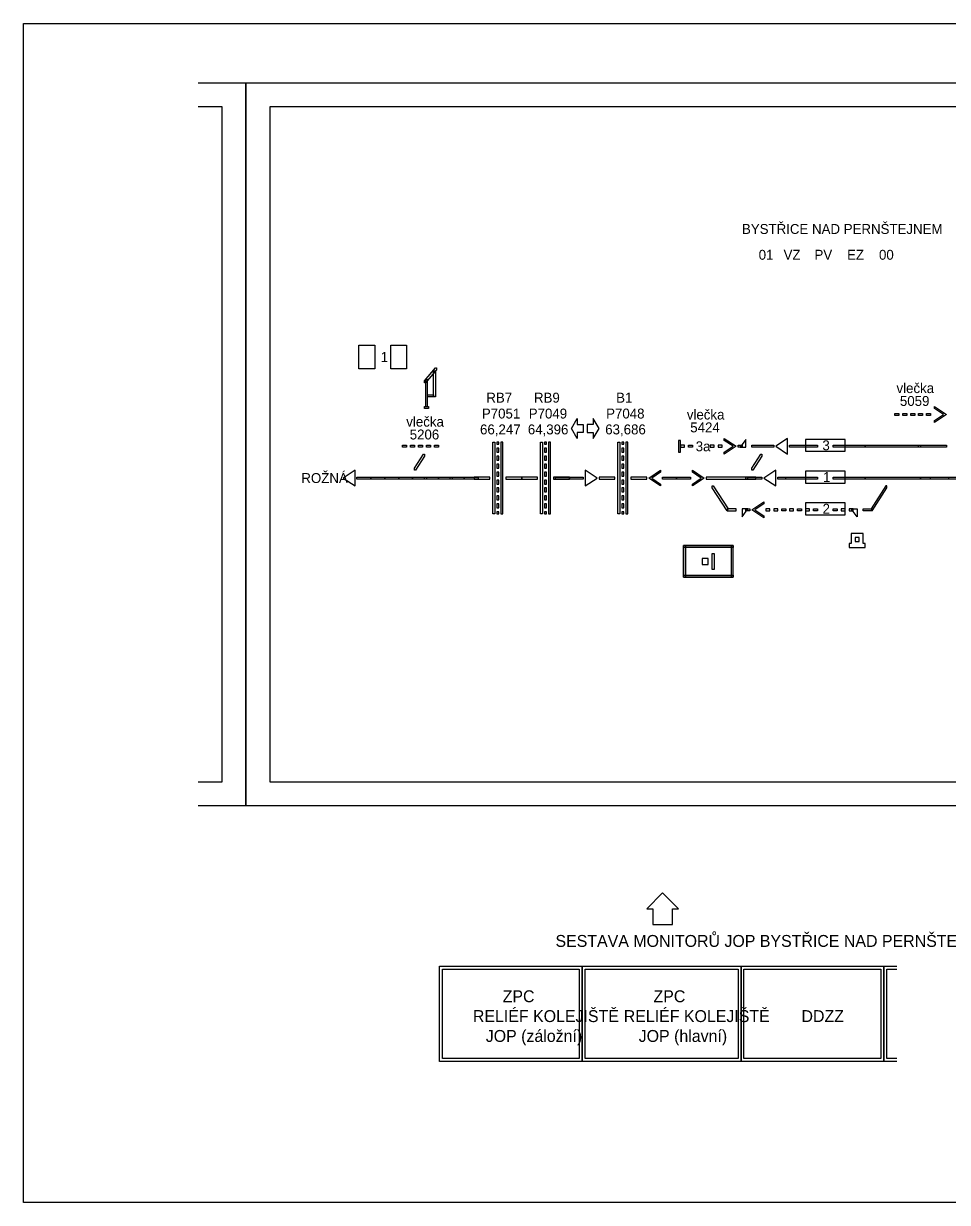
# Model space of a CAD drawing. Extents: x -1424 to 5155, y -2900 to 2050.
# Drawn here: x 2740 to 2972.8, y -2350 to -2053 of the extents above; entities that cross this region are included whole.
import ezdxf

# ---------------------------------------------------------------- set-up
doc = ezdxf.new("R2010")
doc.units = 0
doc.layers.add('Vrstva 1', color=7, linetype='Continuous')
doc.layers.add('Vrstva 2', color=7, linetype='Continuous')

msp = doc.modelspace()

# ---------------------------------------------------------------- linework, layer by layer
for points in [[(2784, -2250), (2796, -2250), (2796, -2068), (2784, -2068)], [(2784, -2244), (2790, -2244), (2790, -2074), (2784, -2074)], [(2960, -2314.5), (2956.75, -2314.5), (2956.75, -2290.5), (2960, -2290.5)], [(2960, -2313.75), (2957.5, -2313.75), (2957.5, -2291.25), (2960, -2291.25)]]:
    msp.add_lwpolyline(points)
for points in [[(2796, -2250), (3108, -2250), (3108, -2068), (2796, -2068)], [(2802, -2244), (3102, -2244), (3102, -2074), (2802, -2074)], [(2901, -2272), (2897, -2276), (2898.5, -2276), (2898.5, -2280), (2903.5, -2280), (2903.5, -2276), (2905, -2276)], [(2844.75, -2290.5), (2880.75, -2290.5), (2880.75, -2314.5), (2844.75, -2314.5)], [(2845.5, -2291.25), (2880, -2291.25), (2880, -2313.75), (2845.5, -2313.75)], [(2880.75, -2290.5), (2920.75, -2290.5), (2920.75, -2314.5), (2880.75, -2314.5)], [(2881.5, -2291.25), (2920, -2291.25), (2920, -2313.75), (2881.5, -2313.75)], [(2920.75, -2290.5), (2956.75, -2290.5), (2956.75, -2314.5), (2920.75, -2314.5)], [(2921.5, -2291.25), (2956, -2291.25), (2956, -2313.75), (2921.5, -2313.75)]]:
    msp.add_lwpolyline(points, close=True)
at = {"layer": 'Vrstva 1'}
for points in [[(3160, -2350), (2740, -2350), (2740, -2053), (3160, -2053)], [(2841.25, -2143.5), (2841, -2143.5), (2841, -2143), (2843.75, -2139.75), (2844, -2139.75), (2844, -2140.25)], [(2843.25, -2140.5), (2843.75, -2140.5), (2843.75, -2147), (2843.25, -2147)], [(2841, -2143.5), (2841.25, -2143.25), (2841.25, -2143.25), (2841.25, -2143.25)], [(2841.75, -2142.75), (2841.25, -2142.75), (2841.25, -2149.5), (2841.75, -2149.5)], [(2841.75, -2146.5), (2843.25, -2146.5), (2843.25, -2147), (2841.75, -2147)], [(2841, -2149.5), (2842, -2149.5), (2842, -2150), (2841, -2150)], [(2969.5, -2149.5), (2972.5, -2151.5), (2969.5, -2153.5), (2969.5, -2153), (2971.75, -2151.5), (2969.5, -2150)], [(2881, -2154), (2881, -2156), (2879.5, -2156), (2879.5, -2157.5), (2878, -2155), (2879.5, -2152.5), (2879.5, -2154)], [(2882, -2154), (2882, -2156), (2883.5, -2156), (2883.5, -2157.5), (2885, -2155), (2883.5, -2152.5), (2883.5, -2154)], [(2960.5, -2151.75), (2959.5, -2151.75), (2959.5, -2151.25), (2960.5, -2151.25)], [(2962.5, -2151.75), (2961.5, -2151.75), (2961.5, -2151.25), (2962.5, -2151.25)], [(2964.5, -2151.75), (2963.5, -2151.75), (2963.5, -2151.25), (2964.5, -2151.25)], [(2966.5, -2151.75), (2965.5, -2151.75), (2965.5, -2151.25), (2966.5, -2151.25)], [(2968.5, -2151.75), (2967.5, -2151.75), (2967.5, -2151.25), (2968.5, -2151.25)], [(2858.75, -2176.5), (2858.25, -2176.5), (2858.25, -2158.5), (2858.75, -2158.5)], [(2859.75, -2158.5), (2859.25, -2158.5), (2859.25, -2159), (2859.75, -2159)], [(2860.75, -2158.5), (2860.25, -2158.5), (2860.25, -2176.5), (2860.75, -2176.5)], [(2870.75, -2176.5), (2870.25, -2176.5), (2870.25, -2158.5), (2870.75, -2158.5)], [(2871.75, -2158.5), (2871.25, -2158.5), (2871.25, -2159), (2871.75, -2159)], [(2872.75, -2158.5), (2872.25, -2158.5), (2872.25, -2176.5), (2872.75, -2176.5)], [(2890.25, -2176.5), (2889.75, -2176.5), (2889.75, -2158.5), (2890.25, -2158.5)], [(2891.25, -2158.5), (2890.75, -2158.5), (2890.75, -2159), (2891.25, -2159)], [(2892.25, -2158.5), (2891.75, -2158.5), (2891.75, -2176.5), (2892.25, -2176.5)], [(2905, -2161), (2905.5, -2161), (2905.5, -2158), (2905, -2158)], [(2916.5, -2157.5), (2919.5, -2159.5), (2916.5, -2161.5), (2916.5, -2161), (2918.75, -2159.5), (2916.5, -2158)], [(2922, -2159.75), (2922, -2157.75), (2920.5, -2159.75)], [(2922, -2159.75), (2922, -2157.75), (2920.5, -2159.75)], [(2932.5, -2161.5), (2932.5, -2157.5), (2929.5, -2159.5)], [(2937, -2160.75), (2947, -2160.75), (2947, -2157.75), (2937, -2157.75)], [(2937, -2160.75), (2947, -2160.75), (2947, -2157.75), (2937, -2157.75)], [(2836.5, -2159.75), (2835.5, -2159.75), (2835.5, -2159.25), (2836.5, -2159.25)], [(2838.5, -2159.75), (2837.5, -2159.75), (2837.5, -2159.25), (2838.5, -2159.25)], [(2838.5, -2165.5), (2838.5, -2165), (2840.75, -2161.5), (2841, -2161.5), (2841, -2162), (2838.75, -2165.5)], [(2840.5, -2159.75), (2839.5, -2159.75), (2839.5, -2159.25), (2840.5, -2159.25)], [(2842.5, -2159.75), (2841.5, -2159.75), (2841.5, -2159.25), (2842.5, -2159.25)], [(2844.5, -2159.75), (2843.5, -2159.75), (2843.5, -2159.25), (2844.5, -2159.25)], [(2859.75, -2160), (2859.25, -2160), (2859.25, -2161), (2859.75, -2161)], [(2859.75, -2162), (2859.25, -2162), (2859.25, -2163), (2859.75, -2163)], [(2871.75, -2160), (2871.25, -2160), (2871.25, -2161), (2871.75, -2161)], [(2871.75, -2162), (2871.25, -2162), (2871.25, -2163), (2871.75, -2163)], [(2891.25, -2160), (2890.75, -2160), (2890.75, -2161), (2891.25, -2161)], [(2891.25, -2162), (2890.75, -2162), (2890.75, -2163), (2891.25, -2163)], [(2905.49, -2159.75), (2906.49, -2159.75), (2906.49, -2159.25), (2905.49, -2159.25)], [(2905.49, -2159.75), (2906.49, -2159.75), (2906.49, -2159.25), (2905.49, -2159.25)], [(2907.5, -2159.25), (2908.5, -2159.25), (2908.5, -2159.75), (2907.5, -2159.75)], [(2907.5, -2159.25), (2908.5, -2159.25), (2908.5, -2159.75), (2907.5, -2159.75)], [(2907.5, -2159.25), (2908.5, -2159.25), (2908.5, -2159.75), (2907.5, -2159.75)], [(2912.99, -2159.75), (2913.99, -2159.75), (2913.99, -2159.25), (2912.99, -2159.25)], [(2914.99, -2159.75), (2915.99, -2159.75), (2915.99, -2159.25), (2914.99, -2159.25)], [(2921, -2159.75), (2920, -2159.75), (2920, -2159.25), (2921, -2159.25)], [(2921, -2159.75), (2920, -2159.75), (2920, -2159.25), (2921, -2159.25)], [(2929, -2159.75), (2923.5, -2159.75), (2923.5, -2159.25), (2929, -2159.25)], [(2923.5, -2165.5), (2923.5, -2165), (2925.75, -2161.5), (2926, -2161.5), (2926, -2162), (2923.75, -2165.5)], [(2940, -2159.75), (2933, -2159.75), (2933, -2159.25), (2940, -2159.25)], [(2952, -2159.75), (2944, -2159.75), (2944, -2159.25), (2952, -2159.25)], [(2966, -2159.75), (2952, -2159.75), (2952, -2159.25), (2966, -2159.25)], [(2972.5, -2159.75), (2965.5, -2159.75), (2965.5, -2159.25), (2972.5, -2159.25)], [(2859.75, -2164), (2859.25, -2164), (2859.25, -2165), (2859.75, -2165)], [(2871.75, -2164), (2871.25, -2164), (2871.25, -2165), (2871.75, -2165)], [(2891.25, -2164), (2890.75, -2164), (2890.75, -2165), (2891.25, -2165)], [(2823.5, -2169.5), (2823.5, -2165.5), (2820.5, -2167.5)], [(2827.5, -2167.75), (2824, -2167.75), (2824, -2167.25), (2827.5, -2167.25)], [(2831, -2167.75), (2827.5, -2167.75), (2827.5, -2167.25), (2831, -2167.25)], [(2834.5, -2167.75), (2831, -2167.75), (2831, -2167.25), (2834.5, -2167.25)], [(2838, -2167.75), (2834.5, -2167.75), (2834.5, -2167.25), (2838, -2167.25)], [(2841.5, -2167.75), (2838, -2167.75), (2838, -2167.25), (2841.5, -2167.25)], [(2844.5, -2167.75), (2841, -2167.75), (2841, -2167.25), (2844.5, -2167.25)], [(2848, -2167.75), (2844.5, -2167.75), (2844.5, -2167.25), (2848, -2167.25)], [(2851, -2167.75), (2847.5, -2167.75), (2847.5, -2167.25), (2851, -2167.25)], [(2854.5, -2167.75), (2851, -2167.75), (2851, -2167.25), (2854.5, -2167.25)], [(2857.5, -2167.25), (2853.5, -2167.25), (2853.5, -2167.75), (2857.5, -2167.75)], [(2859.75, -2166), (2859.25, -2166), (2859.25, -2167), (2859.75, -2167)], [(2859.75, -2168), (2859.25, -2168), (2859.25, -2169), (2859.75, -2169)], [(2865.5, -2167.25), (2861.5, -2167.25), (2861.5, -2167.75), (2865.5, -2167.75)], [(2869.5, -2167.25), (2865.5, -2167.25), (2865.5, -2167.75), (2869.5, -2167.75)], [(2871.75, -2166), (2871.25, -2166), (2871.25, -2167), (2871.75, -2167)], [(2871.75, -2168), (2871.25, -2168), (2871.25, -2169), (2871.75, -2169)], [(2877.5, -2167.25), (2873.5, -2167.25), (2873.5, -2167.75), (2877.5, -2167.75)], [(2877.5, -2167.75), (2874, -2167.75), (2874, -2167.25), (2877.5, -2167.25)], [(2881, -2167.75), (2877.5, -2167.75), (2877.5, -2167.25), (2881, -2167.25)], [(2881.5, -2165.5), (2881.5, -2169.5), (2884.5, -2167.5)], [(2881.5, -2165.5), (2881.5, -2169.5), (2884.5, -2167.5)], [(2889, -2167.25), (2885, -2167.25), (2885, -2167.75), (2889, -2167.75)], [(2891.25, -2166), (2890.75, -2166), (2890.75, -2167), (2891.25, -2167)], [(2891.25, -2168), (2890.75, -2168), (2890.75, -2169), (2891.25, -2169)], [(2897, -2167.25), (2893, -2167.25), (2893, -2167.75), (2897, -2167.75)], [(2900.5, -2169.5), (2897.5, -2167.5), (2900.5, -2165.5), (2900.5, -2166), (2898.25, -2167.5), (2900.5, -2169)], [(2904.5, -2167.75), (2901, -2167.75), (2901, -2167.25), (2904.5, -2167.25)], [(2908, -2167.75), (2904.5, -2167.75), (2904.5, -2167.25), (2908, -2167.25)], [(2908, -2167.75), (2904.5, -2167.75), (2904.5, -2167.25), (2908, -2167.25)], [(2908.5, -2165.5), (2911.5, -2167.5), (2908.5, -2169.5), (2908.5, -2169), (2910.75, -2167.5), (2908.5, -2166)], [(2908.5, -2165.5), (2911.5, -2167.5), (2908.5, -2169.5), (2908.5, -2169), (2910.75, -2167.5), (2908.5, -2166)], [(2912, -2167.75), (2922, -2167.75), (2922, -2167.25), (2912, -2167.25)], [(2924.5, -2167.25), (2922, -2167.25), (2922, -2167.75), (2924.5, -2167.75)], [(2926, -2167.75), (2922.5, -2167.75), (2922.5, -2167.25), (2926, -2167.25)], [(2929.5, -2169.5), (2929.5, -2165.5), (2926.5, -2167.5)], [(2940, -2167.75), (2930, -2167.75), (2930, -2167.25), (2940, -2167.25)], [(2940, -2167.75), (2932, -2167.75), (2932, -2167.25), (2940, -2167.25)], [(2937, -2168.75), (2947, -2168.75), (2947, -2165.75), (2937, -2165.75)], [(2937, -2168.75), (2947, -2168.75), (2947, -2165.75), (2937, -2165.75)], [(2952, -2167.75), (2944, -2167.75), (2944, -2167.25), (2952, -2167.25)], [(2966, -2167.75), (2952, -2167.75), (2952, -2167.25), (2966, -2167.25)], [(2973, -2167.75), (2966, -2167.75), (2966, -2167.25), (2973, -2167.25)], [(2975.5, -2167.75), (2968.5, -2167.75), (2968.5, -2167.25), (2975.5, -2167.25)], [(2859.75, -2170), (2859.25, -2170), (2859.25, -2171), (2859.75, -2171)], [(2871.75, -2170), (2871.25, -2170), (2871.25, -2171), (2871.75, -2171)], [(2891.25, -2170), (2890.75, -2170), (2890.75, -2171), (2891.25, -2171)], [(2913.5, -2170), (2913.5, -2169.5), (2913.75, -2169.5), (2917.5, -2175.25), (2917.25, -2175.75)], [(2913.5, -2170), (2913.5, -2169.5), (2913.75, -2169.5), (2917.5, -2175.25), (2917.25, -2175.75)], [(2957.5, -2170), (2957.5, -2169.5), (2957.25, -2169.5), (2953.5, -2175.25), (2953.75, -2175.75)], [(2859.75, -2172), (2859.25, -2172), (2859.25, -2173), (2859.75, -2173)], [(2859.75, -2174), (2859.25, -2174), (2859.25, -2175), (2859.75, -2175)], [(2871.75, -2172), (2871.25, -2172), (2871.25, -2173), (2871.75, -2173)], [(2871.75, -2174), (2871.25, -2174), (2871.25, -2175), (2871.75, -2175)], [(2891.25, -2172), (2890.75, -2172), (2890.75, -2173), (2891.25, -2173)], [(2891.25, -2174), (2890.75, -2174), (2890.75, -2175), (2891.25, -2175)], [(2926.5, -2177.5), (2923.5, -2175.5), (2926.5, -2173.5), (2926.5, -2174), (2924.25, -2175.5), (2926.5, -2177)], [(2937, -2176.75), (2947, -2176.75), (2947, -2173.75), (2937, -2173.75)], [(2937, -2176.75), (2947, -2176.75), (2947, -2173.75), (2937, -2173.75)], [(2859.75, -2176), (2859.25, -2176), (2859.25, -2176.5), (2859.75, -2176.5)], [(2871.75, -2176), (2871.25, -2176), (2871.25, -2176.5), (2871.75, -2176.5)], [(2891.25, -2176), (2890.75, -2176), (2890.75, -2176.5), (2891.25, -2176.5)], [(2919.5, -2175.25), (2917.25, -2175.25), (2917.25, -2175.75), (2919.5, -2175.75)], [(2921, -2175.25), (2921, -2177.25), (2922.5, -2175.25)], [(2921, -2175.25), (2921, -2177.25), (2922.5, -2175.25)], [(2922, -2175.25), (2923, -2175.25), (2923, -2175.75), (2922, -2175.75)], [(2922, -2175.25), (2923, -2175.25), (2923, -2175.75), (2922, -2175.75)], [(2926.99, -2175.75), (2927.99, -2175.75), (2927.99, -2175.25), (2926.99, -2175.25)], [(2926.99, -2175.75), (2927.99, -2175.75), (2927.99, -2175.25), (2926.99, -2175.25)], [(2928.99, -2175.75), (2929.99, -2175.75), (2929.99, -2175.25), (2928.99, -2175.25)], [(2931, -2175.25), (2932, -2175.25), (2932, -2175.75), (2931, -2175.75)], [(2931, -2175.25), (2932, -2175.25), (2932, -2175.75), (2931, -2175.75)], [(2931, -2175.25), (2932, -2175.25), (2932, -2175.75), (2931, -2175.75)], [(2931, -2175.25), (2932, -2175.25), (2932, -2175.75), (2931, -2175.75)], [(2932.99, -2175.75), (2933.99, -2175.75), (2933.99, -2175.25), (2932.99, -2175.25)], [(2932.99, -2175.75), (2933.99, -2175.75), (2933.99, -2175.25), (2932.99, -2175.25)], [(2935, -2175.25), (2936, -2175.25), (2936, -2175.75), (2935, -2175.75)], [(2935, -2175.25), (2936, -2175.25), (2936, -2175.75), (2935, -2175.75)], [(2935, -2175.25), (2936, -2175.25), (2936, -2175.75), (2935, -2175.75)], [(2935, -2175.25), (2936, -2175.25), (2936, -2175.75), (2935, -2175.75)], [(2936.99, -2175.75), (2937.99, -2175.75), (2937.99, -2175.25), (2936.99, -2175.25)], [(2936.99, -2175.75), (2937.99, -2175.75), (2937.99, -2175.25), (2936.99, -2175.25)], [(2939, -2175.25), (2940, -2175.25), (2940, -2175.75), (2939, -2175.75)], [(2939, -2175.25), (2940, -2175.25), (2940, -2175.75), (2939, -2175.75)], [(2939, -2175.25), (2940, -2175.25), (2940, -2175.75), (2939, -2175.75)], [(2939, -2175.25), (2940, -2175.25), (2940, -2175.75), (2939, -2175.75)], [(2944, -2175.25), (2945, -2175.25), (2945, -2175.75), (2944, -2175.75)], [(2944, -2175.25), (2945, -2175.25), (2945, -2175.75), (2944, -2175.75)], [(2947, -2175.25), (2946, -2175.25), (2946, -2175.75), (2947, -2175.75)], [(2947, -2175.25), (2946, -2175.25), (2946, -2175.75), (2947, -2175.75)], [(2949, -2175.25), (2948, -2175.25), (2948, -2175.75), (2949, -2175.75)], [(2949, -2175.25), (2948, -2175.25), (2948, -2175.75), (2949, -2175.75)], [(2950, -2175.25), (2950, -2177.25), (2948.5, -2175.25)], [(2950, -2175.25), (2950, -2177.25), (2948.5, -2175.25)], [(2951.5, -2175.25), (2953.75, -2175.25), (2953.75, -2175.75), (2951.5, -2175.75)], [(2948, -2185), (2952, -2185), (2952, -2184), (2951.5, -2184), (2951.5, -2181.5), (2948.5, -2181.5), (2948.5, -2184), (2948, -2184)], [(2949.5, -2183.5), (2950.5, -2183.5), (2950.5, -2182.5), (2949.5, -2182.5)], [(2918.75, -2192.5), (2918.75, -2184.5), (2906.25, -2184.5), (2906.25, -2192.5)], [(2918.75, -2184.5), (2918.75, -2185), (2906.25, -2185), (2906.25, -2184.5)], [(2906.25, -2192.5), (2906.25, -2184.5), (2906.75, -2184.5), (2906.75, -2192.5)], [(2918.75, -2192.5), (2918.75, -2184.5), (2906.25, -2184.5), (2906.25, -2192.5)], [(2918.75, -2184.5), (2918.75, -2185), (2906.25, -2185), (2906.25, -2184.5)], [(2906.25, -2192.5), (2906.25, -2184.5), (2906.75, -2184.5), (2906.75, -2192.5)], [(2918.75, -2192.5), (2918.75, -2184.5), (2918.25, -2184.5), (2918.25, -2192.5)], [(2918.75, -2192.5), (2918.75, -2184.5), (2918.25, -2184.5), (2918.25, -2192.5)], [(2912.5, -2189.25), (2912.5, -2187.75), (2911, -2187.75), (2911, -2189.25)], [(2912.5, -2189.25), (2912.5, -2187.75), (2911, -2187.75), (2911, -2189.25)], [(2913.5, -2190.5), (2913.5, -2186.5), (2914, -2186.5), (2914, -2190.5)], [(2913.5, -2190.5), (2913.5, -2186.5), (2914, -2186.5), (2914, -2190.5)], [(2918.75, -2192), (2918.75, -2192.5), (2906.25, -2192.5), (2906.25, -2192)], [(2918.75, -2192), (2918.75, -2192.5), (2906.25, -2192.5), (2906.25, -2192)]]:
    msp.add_lwpolyline(points, close=True, dxfattribs=at)
at = {"layer": 'Vrstva 2'}
for points in [[(2824.5, -2134), (2828.5, -2134), (2828.5, -2140), (2824.5, -2140)], [(2832.5, -2134), (2836.5, -2134), (2836.5, -2140), (2832.5, -2140)]]:
    msp.add_lwpolyline(points, close=True, dxfattribs=at)

# ---------------------------------------------------------------- texts
msp.add_text('SESTAVA MONITORŮ JOP BYSTŘICE NAD PERNŠTEJNEM', height=3).set_placement((2874, -2285.62))
at = {"layer": 'Vrstva 1'}
for s, p in [('BYSTŘICE NAD PERNŠTEJNEM', (2920.99, -2106)), ('3a', (2909.33, -2160.75)), ('3', (2941.25, -2160.5)), ('1', (2941.42, -2168.5)), ('2', (2941.3, -2176.5))]:
    msp.add_text(s, height=2.5, rotation=360, dxfattribs=at).set_placement(p)
for s, height, p in [('01', 2.5, (2925.2, -2112.5)), ('VZ', 2.5, (2931.47, -2112.5)), ('PV', 2.5, (2939.26, -2112.5)), ('EZ', 2.5, (2947.47, -2112.5)), ('00', 2.5, (2955.51, -2112.5)), ('1', 2.5, (2829.97, -2138.25)), ('vlečka', 2.5, (2959.92, -2146.09)), ('RB7', 2.5, (2856.59, -2148.5)), ('RB9', 2.5, (2868.59, -2148.5)), ('B1', 2.5, (2889.29, -2148.5)), ('5059', 2.5, (2960.78, -2149.33)), ('P7051', 2.5, (2855.46, -2152.5)), ('P7049', 2.5, (2867.27, -2152.5)), ('P7048', 2.5, (2886.77, -2152.5)), ('vlečka', 2.5, (2907.1, -2152.75)), ('vlečka', 2.5, (2836.42, -2154.55)), ('5206', 2.5, (2837.28, -2157.78)), ('66,247', 2.5, (2855, -2156.5)), ('64,396', 2.5, (2867.04, -2156.5)), ('63,686', 2.5, (2886.54, -2156.5)), ('5424', 2.5, (2907.96, -2155.99)), ('ROŽNÁ', 2.5, (2809.98, -2168.75)), ('ZPC', 3, (2860.7, -2299.56)), ('ZPC', 3, (2898.7, -2299.56)), ('RELIÉF KOLEJIŠTĚ', 3, (2853.2, -2304.56)), ('RELIÉF KOLEJIŠTĚ', 3, (2891.2, -2304.56)), ('DDZZ', 3, (2935.98, -2304.56)), ('JOP (záložní)', 3, (2856.44, -2309.56)), ('JOP (hlavní)', 3, (2894.97, -2309.56))]:
    msp.add_text(s, height=height, dxfattribs=at).set_placement(p)

doc.saveas('drawing.dxf')
